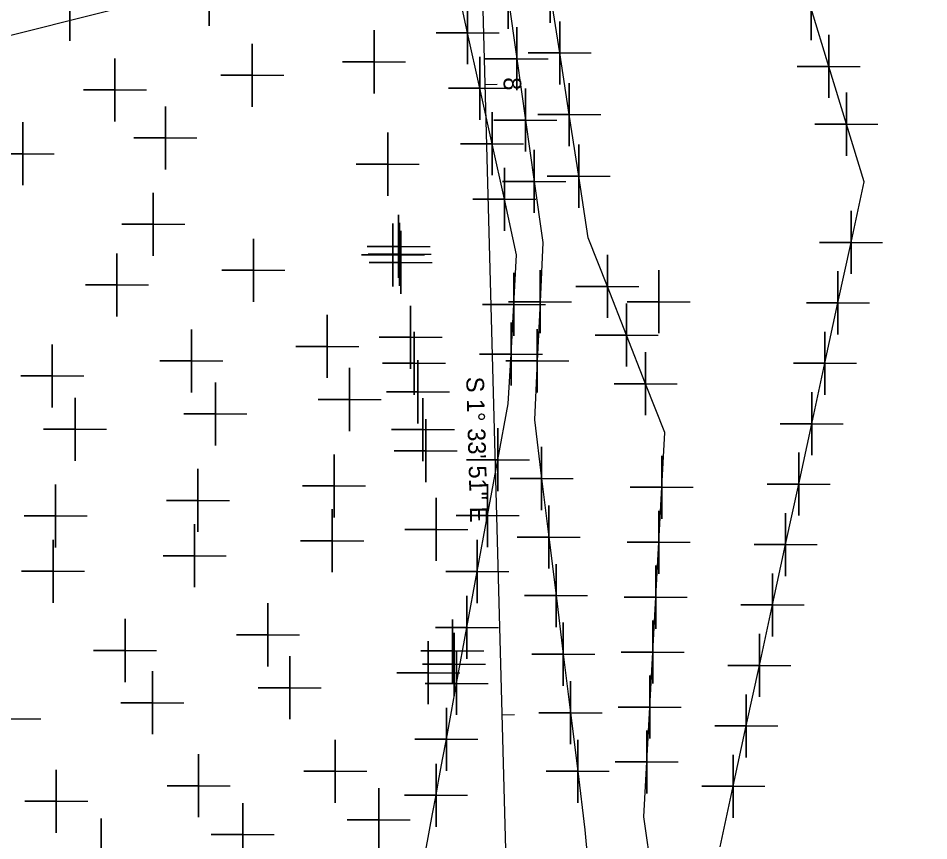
# Model space of a CAD drawing. Extents: x 2260968 to 2264340, y 653057 to 655850.
# Drawn here: x 2261677.5 to 2261749.7, y 654928.3 to 654993.6 of the extents above; entities that cross this region are included whole.
import ezdxf

# ---------------------------------------------------------------- set-up
doc = ezdxf.new("R2010")
doc.units = 0
for name, color, linetype in [('CL_X_Construction', 7, 'Continuous'), ('Default', 7, 'Continuous'), ('GE_X_CL_10', 7, 'Continuous'), ('GK_Patterns2', 7, 'Continuous')]:
    doc.layers.add(name, color=color, linetype=linetype)

msp = doc.modelspace()

# ---------------------------------------------------------------- linework, layer by layer
at = {"layer": 'CL_X_Construction'}
msp.add_line((2261714.109, 655001.598), (2261716.474, 654914.987), dxfattribs=at)
msp.add_line((2261714.109, 655001.598), (2261716.474, 654914.987), dxfattribs=at)
at = {"layer": 'Default'}
for points in [[(2261692.61, 654995.47), (2261692.61, 654997.97), (2261692.61, 654995.47), (2261690.11, 654995.47), (2261692.61, 654995.47), (2261692.61, 654992.97), (2261692.61, 654995.47), (2261695.11, 654995.47)], [(2261716.321, 654995.21), (2261716.321, 654997.71), (2261716.321, 654995.21), (2261713.821, 654995.21), (2261716.321, 654995.21), (2261716.321, 654992.71), (2261716.321, 654995.21), (2261718.821, 654995.21)], [(2261719.672, 654995.689), (2261719.672, 654998.189), (2261719.672, 654995.689), (2261717.172, 654995.689), (2261719.672, 654995.689), (2261719.672, 654993.189), (2261719.672, 654995.689), (2261722.172, 654995.689)], [(2261681.55, 654994.26), (2261681.55, 654996.76), (2261681.55, 654994.26), (2261679.05, 654994.26), (2261681.55, 654994.26), (2261681.55, 654991.76), (2261681.55, 654994.26), (2261684.05, 654994.26)], [(2261709.802, 654927.594), (2261710.333, 654930.466), (2261710.608, 654931.954), (2261710.816, 654933.08), (2261711.131, 654934.784), (2261711.427, 654936.388), (2261711.832, 654938.58), (2261712.243, 654940.803), (2261712.246, 654940.822), (2261713.066, 654945.256), (2261713.885, 654949.691), (2261714.704, 654954.125), (2261715.524, 654958.559), (2261716.343, 654962.993), (2261716.563, 654966.932), (2261716.784, 654970.871), (2261717.004, 654974.81), (2261716.033, 654979.211), (2261715.061, 654983.612), (2261714.089, 654988.013), (2261713.118, 654992.413), (2261712.146, 654996.814)], [(2261740.364, 654994.327), (2261740.364, 654996.827), (2261740.364, 654994.327), (2261737.864, 654994.327), (2261740.364, 654994.327), (2261740.364, 654991.827), (2261740.364, 654994.327), (2261742.864, 654994.327)], [(2261727.749, 654925.651), (2261727.092, 654930.236), (2261727.33, 654934.591), (2261727.568, 654938.947), (2261727.806, 654943.302), (2261728.044, 654947.658), (2261728.282, 654952.014), (2261728.52, 654956.369), (2261728.758, 654960.725), (2261727.239, 654964.582), (2261725.721, 654968.439), (2261724.202, 654972.297), (2261722.683, 654976.154), (2261721.931, 654981.038), (2261721.178, 654985.921), (2261720.425, 654990.805), (2261719.672, 654995.689)], [(2261713.118, 654992.413), (2261713.118, 654994.913), (2261713.118, 654992.413), (2261710.618, 654992.413), (2261713.118, 654992.413), (2261713.118, 654989.913), (2261713.118, 654992.413), (2261715.618, 654992.413)], [(2261716.321, 654995.21), (2261717.012, 654990.35), (2261717.703, 654985.489), (2261718.393, 654980.628), (2261719.084, 654975.767), (2261718.859, 654971.081), (2261718.634, 654966.394), (2261718.409, 654961.707), (2261718.983, 654957.065), (2261719.556, 654952.423), (2261720.13, 654947.781), (2261720.703, 654943.139), (2261721.277, 654938.496), (2261721.85, 654933.854), (2261722.424, 654929.212), (2261722.853, 654924.316)], [(2261733.147, 654927.866), (2261734.186, 654932.659), (2261735.224, 654937.451), (2261736.262, 654942.243), (2261737.3, 654947.036), (2261738.339, 654951.828), (2261739.377, 654956.62), (2261740.415, 654961.413), (2261741.454, 654966.205), (2261742.492, 654970.997), (2261743.53, 654975.79), (2261744.568, 654980.582), (2261743.167, 654985.164), (2261741.766, 654989.745), (2261740.364, 654994.327)], [(2261705.694, 654990.103), (2261705.694, 654992.603), (2261705.694, 654990.103), (2261703.194, 654990.103), (2261705.694, 654990.103), (2261705.694, 654987.603), (2261705.694, 654990.103), (2261708.194, 654990.103)], [(2261717.012, 654990.35), (2261717.012, 654992.85), (2261717.012, 654990.35), (2261714.512, 654990.35), (2261717.012, 654990.35), (2261717.012, 654987.85), (2261717.012, 654990.35), (2261719.512, 654990.35)], [(2261720.425, 654990.805), (2261720.425, 654993.305), (2261720.425, 654990.805), (2261717.925, 654990.805), (2261720.425, 654990.805), (2261720.425, 654988.305), (2261720.425, 654990.805), (2261722.925, 654990.805)], [(2261741.766, 654989.745), (2261741.766, 654992.245), (2261741.766, 654989.745), (2261739.266, 654989.745), (2261741.766, 654989.745), (2261741.766, 654987.245), (2261741.766, 654989.745), (2261744.266, 654989.745)], [(2261696.03, 654989.04), (2261696.03, 654991.54), (2261696.03, 654989.04), (2261693.53, 654989.04), (2261696.03, 654989.04), (2261696.03, 654986.54), (2261696.03, 654989.04), (2261698.53, 654989.04)], [(2261714.089, 654988.013), (2261714.089, 654990.513), (2261714.089, 654988.013), (2261711.589, 654988.013), (2261714.089, 654988.013), (2261714.089, 654985.513), (2261714.089, 654988.013), (2261716.589, 654988.013)], [(2261685.14, 654987.88), (2261685.14, 654990.38), (2261685.14, 654987.88), (2261682.64, 654987.88), (2261685.14, 654987.88), (2261685.14, 654985.38), (2261685.14, 654987.88), (2261687.64, 654987.88)], [(2261721.178, 654985.921), (2261721.178, 654988.421), (2261721.178, 654985.921), (2261718.678, 654985.921), (2261721.178, 654985.921), (2261721.178, 654983.421), (2261721.178, 654985.921), (2261723.678, 654985.921)], [(2261717.703, 654985.489), (2261717.703, 654987.989), (2261717.703, 654985.489), (2261715.203, 654985.489), (2261717.703, 654985.489), (2261717.703, 654982.989), (2261717.703, 654985.489), (2261720.203, 654985.489)], [(2261743.167, 654985.164), (2261743.167, 654987.664), (2261743.167, 654985.164), (2261740.667, 654985.164), (2261743.167, 654985.164), (2261743.167, 654982.664), (2261743.167, 654985.164), (2261745.667, 654985.164)], [(2261689.14, 654984.07), (2261689.14, 654986.57), (2261689.14, 654984.07), (2261686.64, 654984.07), (2261689.14, 654984.07), (2261689.14, 654981.57), (2261689.14, 654984.07), (2261691.64, 654984.07)], [(2261715.061, 654983.612), (2261715.061, 654986.112), (2261715.061, 654983.612), (2261712.561, 654983.612), (2261715.061, 654983.612), (2261715.061, 654981.112), (2261715.061, 654983.612), (2261717.561, 654983.612)], [(2261677.82, 654982.82), (2261677.82, 654985.32), (2261677.82, 654982.82), (2261675.32, 654982.82), (2261677.82, 654982.82), (2261677.82, 654980.32), (2261677.82, 654982.82), (2261680.32, 654982.82)], [(2261706.773, 654981.988), (2261706.773, 654984.488), (2261706.773, 654981.988), (2261704.273, 654981.988), (2261706.773, 654981.988), (2261706.773, 654979.488), (2261706.773, 654981.988), (2261709.273, 654981.988)], [(2261721.931, 654981.038), (2261721.931, 654983.538), (2261721.931, 654981.038), (2261719.431, 654981.038), (2261721.931, 654981.038), (2261721.931, 654978.538), (2261721.931, 654981.038), (2261724.431, 654981.038)], [(2261718.393, 654980.628), (2261718.393, 654983.128), (2261718.393, 654980.628), (2261715.893, 654980.628), (2261718.393, 654980.628), (2261718.393, 654978.128), (2261718.393, 654980.628), (2261720.893, 654980.628)], [(2261716.033, 654979.211), (2261716.033, 654981.711), (2261716.033, 654979.211), (2261713.533, 654979.211), (2261716.033, 654979.211), (2261716.033, 654976.711), (2261716.033, 654979.211), (2261718.533, 654979.211)], [(2261688.18, 654977.22), (2261688.18, 654979.72), (2261688.18, 654977.22), (2261685.68, 654977.22), (2261688.18, 654977.22), (2261688.18, 654974.72), (2261688.18, 654977.22), (2261690.68, 654977.22)], [(2261743.53, 654975.79), (2261743.53, 654978.29), (2261743.53, 654975.79), (2261741.03, 654975.79), (2261743.53, 654975.79), (2261743.53, 654973.29), (2261743.53, 654975.79), (2261746.03, 654975.79)], [(2261707.64, 654975.471), (2261707.64, 654977.971), (2261707.64, 654975.471), (2261705.14, 654975.471), (2261707.64, 654975.471), (2261707.64, 654972.971), (2261707.64, 654975.471), (2261710.14, 654975.471)], [(2261707.19, 654974.79), (2261707.19, 654977.29), (2261707.19, 654974.79), (2261704.69, 654974.79), (2261707.19, 654974.79), (2261707.19, 654972.29), (2261707.19, 654974.79), (2261709.69, 654974.79)], [(2261707.722, 654974.848), (2261707.722, 654977.348), (2261707.722, 654974.848), (2261705.222, 654974.848), (2261707.722, 654974.848), (2261707.722, 654972.348), (2261707.722, 654974.848), (2261710.222, 654974.848)], [(2261707.808, 654974.204), (2261707.808, 654976.704), (2261707.808, 654974.204), (2261705.308, 654974.204), (2261707.808, 654974.204), (2261707.808, 654971.704), (2261707.808, 654974.204), (2261710.308, 654974.204)], [(2261696.12, 654973.58), (2261696.12, 654976.08), (2261696.12, 654973.58), (2261693.62, 654973.58), (2261696.12, 654973.58), (2261696.12, 654971.08), (2261696.12, 654973.58), (2261698.62, 654973.58)], [(2261685.29, 654972.41), (2261685.29, 654974.91), (2261685.29, 654972.41), (2261682.79, 654972.41), (2261685.29, 654972.41), (2261685.29, 654969.91), (2261685.29, 654972.41), (2261687.79, 654972.41)], [(2261724.202, 654972.297), (2261724.202, 654974.797), (2261724.202, 654972.297), (2261721.702, 654972.297), (2261724.202, 654972.297), (2261724.202, 654969.797), (2261724.202, 654972.297), (2261726.702, 654972.297)], [(2261716.784, 654970.871), (2261716.784, 654973.371), (2261716.784, 654970.871), (2261714.284, 654970.871), (2261716.784, 654970.871), (2261716.784, 654968.371), (2261716.784, 654970.871), (2261719.284, 654970.871)], [(2261718.859, 654971.081), (2261718.859, 654973.581), (2261718.859, 654971.081), (2261716.359, 654971.081), (2261718.859, 654971.081), (2261718.859, 654968.581), (2261718.859, 654971.081), (2261721.359, 654971.081)], [(2261728.279, 654971.078), (2261728.279, 654973.578), (2261728.279, 654971.078), (2261725.779, 654971.078), (2261728.279, 654971.078), (2261728.279, 654968.578), (2261728.279, 654971.078), (2261730.779, 654971.078)], [(2261742.492, 654970.997), (2261742.492, 654973.497), (2261742.492, 654970.997), (2261739.992, 654970.997), (2261742.492, 654970.997), (2261742.492, 654968.497), (2261742.492, 654970.997), (2261744.992, 654970.997)], [(2261725.721, 654968.439), (2261725.721, 654970.939), (2261725.721, 654968.439), (2261723.221, 654968.439), (2261725.721, 654968.439), (2261725.721, 654965.939), (2261725.721, 654968.439), (2261728.221, 654968.439)], [(2261708.597, 654968.269), (2261708.597, 654970.769), (2261708.597, 654968.269), (2261706.097, 654968.269), (2261708.597, 654968.269), (2261708.597, 654965.769), (2261708.597, 654968.269), (2261711.097, 654968.269)], [(2261701.98, 654967.54), (2261701.98, 654970.04), (2261701.98, 654967.54), (2261699.48, 654967.54), (2261701.98, 654967.54), (2261701.98, 654965.04), (2261701.98, 654967.54), (2261704.48, 654967.54)], [(2261691.2, 654966.39), (2261691.2, 654968.89), (2261691.2, 654966.39), (2261688.7, 654966.39), (2261691.2, 654966.39), (2261691.2, 654963.89), (2261691.2, 654966.39), (2261693.7, 654966.39)], [(2261716.563, 654966.932), (2261716.563, 654969.432), (2261716.563, 654966.932), (2261714.063, 654966.932), (2261716.563, 654966.932), (2261716.563, 654964.432), (2261716.563, 654966.932), (2261719.063, 654966.932)], [(2261718.634, 654966.394), (2261718.634, 654968.894), (2261718.634, 654966.394), (2261716.134, 654966.394), (2261718.634, 654966.394), (2261718.634, 654963.894), (2261718.634, 654966.394), (2261721.134, 654966.394)], [(2261708.871, 654966.208), (2261708.871, 654968.708), (2261708.871, 654966.208), (2261706.371, 654966.208), (2261708.871, 654966.208), (2261708.871, 654963.708), (2261708.871, 654966.208), (2261711.371, 654966.208)], [(2261741.454, 654966.205), (2261741.454, 654968.705), (2261741.454, 654966.205), (2261738.954, 654966.205), (2261741.454, 654966.205), (2261741.454, 654963.705), (2261741.454, 654966.205), (2261743.954, 654966.205)], [(2261680.16, 654965.2), (2261680.16, 654967.7), (2261680.16, 654965.2), (2261677.66, 654965.2), (2261680.16, 654965.2), (2261680.16, 654962.7), (2261680.16, 654965.2), (2261682.66, 654965.2)], [(2261727.239, 654964.582), (2261727.239, 654967.082), (2261727.239, 654964.582), (2261724.739, 654964.582), (2261727.239, 654964.582), (2261727.239, 654962.082), (2261727.239, 654964.582), (2261729.739, 654964.582)], [(2261709.173, 654963.936), (2261709.173, 654966.436), (2261709.173, 654963.936), (2261706.673, 654963.936), (2261709.173, 654963.936), (2261709.173, 654961.436), (2261709.173, 654963.936), (2261711.673, 654963.936)], [(2261703.75, 654963.33), (2261703.75, 654965.83), (2261703.75, 654963.33), (2261701.25, 654963.33), (2261703.75, 654963.33), (2261703.75, 654960.83), (2261703.75, 654963.33), (2261706.25, 654963.33)], [(2261693.11, 654962.19), (2261693.11, 654964.69), (2261693.11, 654962.19), (2261690.61, 654962.19), (2261693.11, 654962.19), (2261693.11, 654959.69), (2261693.11, 654962.19), (2261695.61, 654962.19)], [(2261740.415, 654961.413), (2261740.415, 654963.913), (2261740.415, 654961.413), (2261737.915, 654961.413), (2261740.415, 654961.413), (2261740.415, 654958.913), (2261740.415, 654961.413), (2261742.915, 654961.413)], [(2261681.98, 654960.97), (2261681.98, 654963.47), (2261681.98, 654960.97), (2261679.48, 654960.97), (2261681.98, 654960.97), (2261681.98, 654958.47), (2261681.98, 654960.97), (2261684.48, 654960.97)], [(2261709.571, 654960.948), (2261709.571, 654963.448), (2261709.571, 654960.948), (2261707.071, 654960.948), (2261709.571, 654960.948), (2261709.571, 654958.448), (2261709.571, 654960.948), (2261712.071, 654960.948)], [(2261709.795, 654959.264), (2261709.795, 654961.764), (2261709.795, 654959.264), (2261707.295, 654959.264), (2261709.795, 654959.264), (2261709.795, 654956.764), (2261709.795, 654959.264), (2261712.295, 654959.264)], [(2261715.524, 654958.559), (2261715.524, 654961.059), (2261715.524, 654958.559), (2261713.024, 654958.559), (2261715.524, 654958.559), (2261715.524, 654956.059), (2261715.524, 654958.559), (2261718.024, 654958.559)], [(2261718.983, 654957.065), (2261718.983, 654959.565), (2261718.983, 654957.065), (2261716.483, 654957.065), (2261718.983, 654957.065), (2261718.983, 654954.565), (2261718.983, 654957.065), (2261721.483, 654957.065)], [(2261702.52, 654956.48), (2261702.52, 654958.98), (2261702.52, 654956.48), (2261700.02, 654956.48), (2261702.52, 654956.48), (2261702.52, 654953.98), (2261702.52, 654956.48), (2261705.02, 654956.48)], [(2261728.52, 654956.369), (2261728.52, 654958.869), (2261728.52, 654956.369), (2261726.02, 654956.369), (2261728.52, 654956.369), (2261728.52, 654953.869), (2261728.52, 654956.369), (2261731.02, 654956.369)], [(2261739.377, 654956.62), (2261739.377, 654959.12), (2261739.377, 654956.62), (2261736.877, 654956.62), (2261739.377, 654956.62), (2261739.377, 654954.12), (2261739.377, 654956.62), (2261741.877, 654956.62)], [(2261691.72, 654955.33), (2261691.72, 654957.83), (2261691.72, 654955.33), (2261689.22, 654955.33), (2261691.72, 654955.33), (2261691.72, 654952.83), (2261691.72, 654955.33), (2261694.22, 654955.33)], [(2261680.43, 654954.1), (2261680.43, 654956.6), (2261680.43, 654954.1), (2261677.93, 654954.1), (2261680.43, 654954.1), (2261680.43, 654951.6), (2261680.43, 654954.1), (2261682.93, 654954.1)], [(2261714.704, 654954.125), (2261714.704, 654956.625), (2261714.704, 654954.125), (2261712.204, 654954.125), (2261714.704, 654954.125), (2261714.704, 654951.625), (2261714.704, 654954.125), (2261717.204, 654954.125)], [(2261710.624, 654953.026), (2261710.624, 654955.526), (2261710.624, 654953.026), (2261708.124, 654953.026), (2261710.624, 654953.026), (2261710.624, 654950.526), (2261710.624, 654953.026), (2261713.124, 654953.026)], [(2261702.37, 654952.13), (2261702.37, 654954.63), (2261702.37, 654952.13), (2261699.87, 654952.13), (2261702.37, 654952.13), (2261702.37, 654949.63), (2261702.37, 654952.13), (2261704.87, 654952.13)], [(2261719.556, 654952.423), (2261719.556, 654954.923), (2261719.556, 654952.423), (2261717.056, 654952.423), (2261719.556, 654952.423), (2261719.556, 654949.923), (2261719.556, 654952.423), (2261722.056, 654952.423)], [(2261728.282, 654952.014), (2261728.282, 654954.514), (2261728.282, 654952.014), (2261725.782, 654952.014), (2261728.282, 654952.014), (2261728.282, 654949.514), (2261728.282, 654952.014), (2261730.782, 654952.014)], [(2261738.339, 654951.828), (2261738.339, 654954.328), (2261738.339, 654951.828), (2261735.839, 654951.828), (2261738.339, 654951.828), (2261738.339, 654949.328), (2261738.339, 654951.828), (2261740.839, 654951.828)], [(2261691.46, 654950.94), (2261691.46, 654953.44), (2261691.46, 654950.94), (2261688.96, 654950.94), (2261691.46, 654950.94), (2261691.46, 654948.44), (2261691.46, 654950.94), (2261693.96, 654950.94)], [(2261680.23, 654949.71), (2261680.23, 654952.21), (2261680.23, 654949.71), (2261677.73, 654949.71), (2261680.23, 654949.71), (2261680.23, 654947.21), (2261680.23, 654949.71), (2261682.73, 654949.71)], [(2261713.885, 654949.691), (2261713.885, 654952.191), (2261713.885, 654949.691), (2261711.385, 654949.691), (2261713.885, 654949.691), (2261713.885, 654947.191), (2261713.885, 654949.691), (2261716.385, 654949.691)], [(2261720.13, 654947.781), (2261720.13, 654950.281), (2261720.13, 654947.781), (2261717.63, 654947.781), (2261720.13, 654947.781), (2261720.13, 654945.281), (2261720.13, 654947.781), (2261722.63, 654947.781)], [(2261728.044, 654947.658), (2261728.044, 654950.158), (2261728.044, 654947.658), (2261725.544, 654947.658), (2261728.044, 654947.658), (2261728.044, 654945.158), (2261728.044, 654947.658), (2261730.544, 654947.658)], [(2261737.3, 654947.036), (2261737.3, 654949.536), (2261737.3, 654947.036), (2261734.8, 654947.036), (2261737.3, 654947.036), (2261737.3, 654944.536), (2261737.3, 654947.036), (2261739.8, 654947.036)], [(2261697.27, 654944.67), (2261697.27, 654947.17), (2261697.27, 654944.67), (2261694.77, 654944.67), (2261697.27, 654944.67), (2261697.27, 654942.17), (2261697.27, 654944.67), (2261699.77, 654944.67)], [(2261713.066, 654945.256), (2261713.066, 654947.756), (2261713.066, 654945.256), (2261710.566, 654945.256), (2261713.066, 654945.256), (2261713.066, 654942.756), (2261713.066, 654945.256), (2261715.566, 654945.256)], [(2261685.94, 654943.43), (2261685.94, 654945.93), (2261685.94, 654943.43), (2261683.44, 654943.43), (2261685.94, 654943.43), (2261685.94, 654940.93), (2261685.94, 654943.43), (2261688.44, 654943.43)], [(2261711.905, 654943.39), (2261711.905, 654945.89), (2261711.905, 654943.39), (2261709.405, 654943.39), (2261711.905, 654943.39), (2261711.905, 654940.89), (2261711.905, 654943.39), (2261714.405, 654943.39)], [(2261727.806, 654943.302), (2261727.806, 654945.802), (2261727.806, 654943.302), (2261725.306, 654943.302), (2261727.806, 654943.302), (2261727.806, 654940.802), (2261727.806, 654943.302), (2261730.306, 654943.302)], [(2261720.703, 654943.139), (2261720.703, 654945.639), (2261720.703, 654943.139), (2261718.203, 654943.139), (2261720.703, 654943.139), (2261720.703, 654940.639), (2261720.703, 654943.139), (2261723.203, 654943.139)], [(2261712.045, 654942.339), (2261712.045, 654944.839), (2261712.045, 654942.339), (2261709.545, 654942.339), (2261712.045, 654942.339), (2261712.045, 654939.839), (2261712.045, 654942.339), (2261714.545, 654942.339)], [(2261736.262, 654942.243), (2261736.262, 654944.743), (2261736.262, 654942.243), (2261733.762, 654942.243), (2261736.262, 654942.243), (2261736.262, 654939.743), (2261736.262, 654942.243), (2261738.762, 654942.243)], [(2261709.99, 654941.66), (2261709.99, 654944.16), (2261709.99, 654941.66), (2261707.49, 654941.66), (2261709.99, 654941.66), (2261709.99, 654939.16), (2261709.99, 654941.66), (2261712.49, 654941.66)], [(2261699.01, 654940.47), (2261699.01, 654942.97), (2261699.01, 654940.47), (2261696.51, 654940.47), (2261699.01, 654940.47), (2261699.01, 654937.97), (2261699.01, 654940.47), (2261701.51, 654940.47)], [(2261712.246, 654940.822), (2261712.246, 654943.322), (2261712.246, 654940.822), (2261709.746, 654940.822), (2261712.246, 654940.822), (2261712.246, 654938.322), (2261712.246, 654940.822), (2261714.746, 654940.822)], [(2261688.11, 654939.29), (2261688.11, 654941.79), (2261688.11, 654939.29), (2261685.61, 654939.29), (2261688.11, 654939.29), (2261688.11, 654936.79), (2261688.11, 654939.29), (2261690.61, 654939.29)], [(2261727.568, 654938.947), (2261727.568, 654941.447), (2261727.568, 654938.947), (2261725.068, 654938.947), (2261727.568, 654938.947), (2261727.568, 654936.447), (2261727.568, 654938.947), (2261730.068, 654938.947)], [(2261721.277, 654938.496), (2261721.277, 654940.996), (2261721.277, 654938.496), (2261718.777, 654938.496), (2261721.277, 654938.496), (2261721.277, 654935.996), (2261721.277, 654938.496), (2261723.777, 654938.496)], [(2261676.75, 654938.02), (2261676.75, 654940.52), (2261676.75, 654938.02), (2261674.25, 654938.02), (2261676.75, 654938.02), (2261676.75, 654935.52), (2261676.75, 654938.02), (2261679.25, 654938.02)], [(2261735.224, 654937.451), (2261735.224, 654939.951), (2261735.224, 654937.451), (2261732.724, 654937.451), (2261735.224, 654937.451), (2261735.224, 654934.951), (2261735.224, 654937.451), (2261737.724, 654937.451)], [(2261711.427, 654936.388), (2261711.427, 654938.888), (2261711.427, 654936.388), (2261708.927, 654936.388), (2261711.427, 654936.388), (2261711.427, 654933.888), (2261711.427, 654936.388), (2261713.927, 654936.388)], [(2261727.33, 654934.591), (2261727.33, 654937.091), (2261727.33, 654934.591), (2261724.83, 654934.591), (2261727.33, 654934.591), (2261727.33, 654932.091), (2261727.33, 654934.591), (2261729.83, 654934.591)], [(2261702.62, 654933.85), (2261702.62, 654936.35), (2261702.62, 654933.85), (2261700.12, 654933.85), (2261702.62, 654933.85), (2261702.62, 654931.35), (2261702.62, 654933.85), (2261705.12, 654933.85)], [(2261721.85, 654933.854), (2261721.85, 654936.354), (2261721.85, 654933.854), (2261719.35, 654933.854), (2261721.85, 654933.854), (2261721.85, 654931.354), (2261721.85, 654933.854), (2261724.35, 654933.854)], [(2261691.77, 654932.7), (2261691.77, 654935.2), (2261691.77, 654932.7), (2261689.27, 654932.7), (2261691.77, 654932.7), (2261691.77, 654930.2), (2261691.77, 654932.7), (2261694.27, 654932.7)], [(2261734.186, 654932.659), (2261734.186, 654935.159), (2261734.186, 654932.659), (2261731.686, 654932.659), (2261734.186, 654932.659), (2261734.186, 654930.159), (2261734.186, 654932.659), (2261736.686, 654932.659)], [(2261710.608, 654931.954), (2261710.608, 654934.454), (2261710.608, 654931.954), (2261708.108, 654931.954), (2261710.608, 654931.954), (2261710.608, 654929.454), (2261710.608, 654931.954), (2261713.108, 654931.954)], [(2261680.48, 654931.47), (2261680.48, 654933.97), (2261680.48, 654931.47), (2261677.98, 654931.47), (2261680.48, 654931.47), (2261680.48, 654928.97), (2261680.48, 654931.47), (2261682.98, 654931.47)], [(2261706.06, 654930), (2261706.06, 654932.5), (2261706.06, 654930), (2261703.56, 654930), (2261706.06, 654930), (2261706.06, 654927.5), (2261706.06, 654930), (2261708.56, 654930)], [(2261695.28, 654928.83), (2261695.28, 654931.33), (2261695.28, 654928.83), (2261692.78, 654928.83), (2261695.28, 654928.83), (2261695.28, 654926.33), (2261695.28, 654928.83), (2261697.78, 654928.83)], [(2261684.05, 654927.6), (2261684.05, 654930.1), (2261684.05, 654927.6), (2261681.55, 654927.6), (2261684.05, 654927.6), (2261684.05, 654925.1), (2261684.05, 654927.6), (2261686.55, 654927.6)]]:
    msp.add_lwpolyline(points, dxfattribs=at)
at = {"layer": 'GE_X_CL_10'}
for p, q in [((2261714.109, 655001.598), (2261716.474, 654914.987)), ((2261714.471, 654988.315), (2261715.471, 654988.342)), ((2261714.471, 654988.315), (2261715.471, 654988.342)), ((2261715.836, 654938.334), (2261716.836, 654938.361)), ((2261715.836, 654938.334), (2261716.836, 654938.361))]:
    msp.add_line(p, q, dxfattribs=at)
at = {"layer": 'GK_Patterns2'}
msp.add_lwpolyline([(2261632.795, 654981.138), (2261714.109, 655001.598), (2261950.979, 655057.107)], dxfattribs=at)

# ---------------------------------------------------------------- texts
at = {"layer": 'GE_X_CL_10'}
for s, p in [('8', (2261715.957, 654988.863)), ('8', (2261715.957, 654988.863)), ('S 1%%d 33\' 51" E', (2261713.004, 654965.116))]:
    msp.add_text(s, height=1.4, rotation=271.56415, dxfattribs=at).set_placement(p)

doc.saveas('drawing.dxf')
